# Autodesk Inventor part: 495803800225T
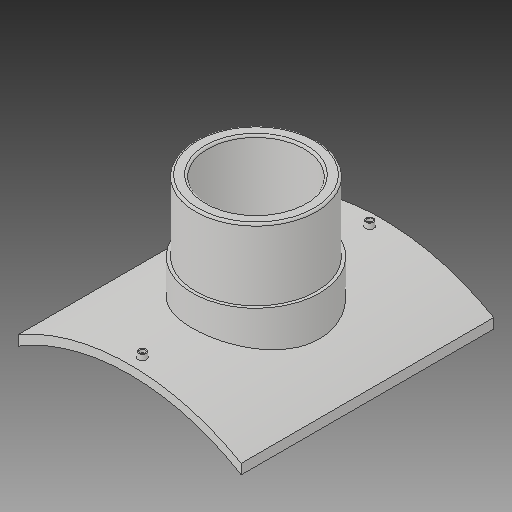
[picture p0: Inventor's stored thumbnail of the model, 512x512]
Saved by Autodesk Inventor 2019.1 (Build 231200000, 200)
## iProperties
Created: 2017-10
Part Number: 495803800225T
Material: Generic
Description: PLASSON BRANCH SADDLE  800x225
Document SubType Name: Modeling
Designer: KIM
Mass: 2754.05 g
Surface Area: 3037.44 cm^2
Volume: 2754.05 cm^3
Density: 1 g/cm^3
Appearance: Default
Author: KIM
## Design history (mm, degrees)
derived "495803.ipt"
feature "Solid1::495803.ipt"
tag "TaggingFeature1"
body "Solid1"
other parameters: "d1" = 16, "d2" = 415, "d4" = 0, "d12" = 425.6, "d13" = 14, "d14" = 211.5, "d16" = 5 deg, "d18" = 4, "d19" = 14, "d20" = 0, "d21" = 3, "d22" = 0, "d23" = 605, "d24" = 236.25, "d25" = 16, "d28" = 0, "d29" = 9.6, "d31" = 0, "d32" = 94.5, "d33" = 0, "d34" = 8, "d36" = 225, "d37" = 132.3, "d38" = 0, "d39" = 4, "d_1" = 225, "B_" = 415, "H_" = 189, "x_" = 16, "D_" = 16
